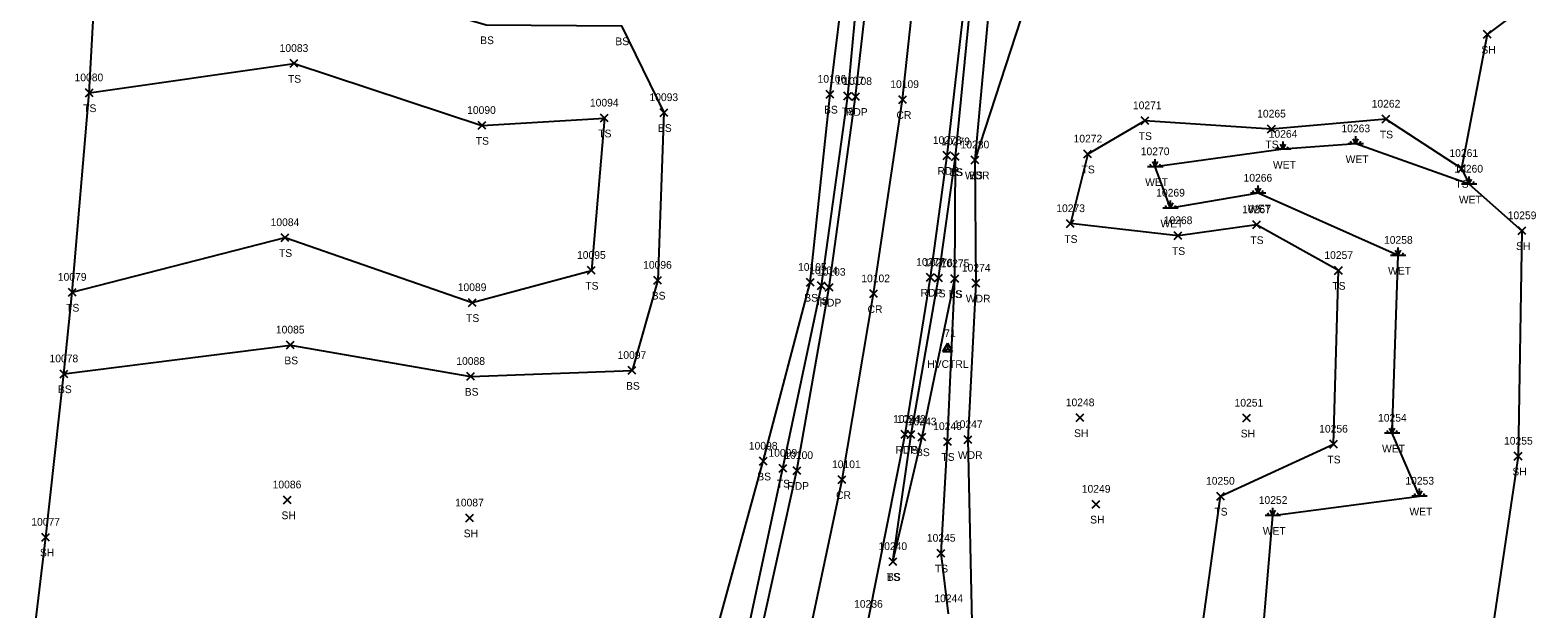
# Model space of a CAD drawing. Extents: x 1482574 to 1485769, y 580696 to 595649.
# Drawn here: x 1484918.2 to 1485309.1, y 580974.9 to 581125.1 of the extents above; entities that cross this region are included whole.
import ezdxf

# ---------------------------------------------------------------- set-up
doc = ezdxf.new("R2010")
doc.units = 0
for name, color, linetype in [('C_A', 7, 'Continuous'), ('C_I', 7, 'Continuous'), ('CPSM', 7, 'Continuous'), ('L_A', 7, 'Continuous'), ('L_I', 7, 'Continuous'), ('L_TIC', 7, 'Continuous'), ('LAWA', 7, 'Continuous'), ('LELB', 7, 'Continuous'), ('LSOGP', 7, 'Continuous'), ('LWET', 7, 'Continuous'), ('P_A', 7, 'Continuous'), ('P_I', 7, 'Continuous'), ('P_TIC', 7, 'Continuous'), ('PET', 7, 'Continuous'), ('PRC', 7, 'Continuous'), ('R_I', 7, 'Continuous')]:
    doc.layers.add(name, color=color, linetype=linetype)

msp = doc.modelspace()

# ---------------------------------------------------------------- linework, layer by layer
at = {"layer": 'CPSM'}
for p, q in [((1485154.86, 581041.75), (1485156.11, 581043.92)), ((1485154.86, 581041.75), (1485156.11, 581042.47)), ((1485154.86, 581041.75), (1485157.36, 581041.75)), ((1485157.36, 581041.75), (1485156.11, 581043.92)), ((1485156.11, 581042.47), (1485156.11, 581043.92)), ((1485156.11, 581042.47), (1485156.11, 581042.47)), ((1485156.11, 581042.47), (1485157.36, 581041.75))]:
    msp.add_line(p, q, dxfattribs=at)
at = {"layer": 'L_TIC'}
for points in [[(1485295, 581123.04), (1485297, 581125.04)], [(1485297, 581123.04), (1485295, 581125.04)], [(1484985.62, 581115.48), (1484987.62, 581117.48)], [(1484987.62, 581115.48), (1484985.62, 581117.48)], [(1484932.52, 581107.86), (1484934.52, 581109.86)], [(1484934.52, 581107.86), (1484932.52, 581109.86)], [(1485124.6, 581107.49), (1485126.6, 581109.49)], [(1485126.6, 581107.49), (1485124.6, 581109.49)], [(1485129.19, 581107.03), (1485131.19, 581109.03)], [(1485131.19, 581107.03), (1485129.19, 581109.03)], [(1485081.52, 581102.72), (1485083.52, 581104.72)], [(1485083.52, 581102.72), (1485081.52, 581104.72)], [(1485034.33, 581099.39), (1485036.33, 581101.39)], [(1485036.33, 581099.39), (1485034.33, 581101.39)], [(1485066.08, 581101.31), (1485068.08, 581103.31)], [(1485068.08, 581101.31), (1485066.08, 581103.31)], [(1485206.23, 581100.62), (1485208.23, 581102.62)], [(1485208.23, 581100.62), (1485206.23, 581102.62)], [(1485239.07, 581098.46), (1485241.07, 581100.46)], [(1485241.07, 581098.46), (1485239.07, 581100.46)], [(1485268.75, 581101.04), (1485270.75, 581103.04)], [(1485270.75, 581101.04), (1485268.75, 581103.04)], [(1485157.09, 581091.27), (1485159.09, 581093.27)], [(1485159.09, 581091.27), (1485157.09, 581093.27)], [(1485157.09, 581091.27), (1485159.09, 581093.27)], [(1485159.09, 581091.27), (1485157.09, 581093.27)], [(1485162.19, 581090.44), (1485164.19, 581092.44)], [(1485164.19, 581090.44), (1485162.19, 581092.44)], [(1485162.19, 581090.44), (1485164.19, 581092.44)], [(1485164.19, 581090.44), (1485162.19, 581092.44)], [(1485191.41, 581091.98), (1485193.41, 581093.98)], [(1485193.41, 581091.98), (1485191.41, 581093.98)], [(1485288.35, 581088.23), (1485290.35, 581090.23)], [(1485290.35, 581088.23), (1485288.35, 581090.23)], [(1485186.93, 581073.91), (1485188.93, 581075.91)], [(1485188.93, 581073.91), (1485186.93, 581075.91)], [(1485186.93, 581073.91), (1485188.93, 581075.91)], [(1485188.93, 581073.91), (1485186.93, 581075.91)], [(1485214.84, 581070.79), (1485216.84, 581072.79)], [(1485216.84, 581070.79), (1485214.84, 581072.79)], [(1485235.19, 581073.62), (1485237.19, 581075.62)], [(1485237.19, 581073.62), (1485235.19, 581075.62)], [(1485303.99, 581072.07), (1485305.99, 581074.07)], [(1485305.99, 581072.07), (1485303.99, 581074.07)], [(1484983.28, 581070.28), (1484985.28, 581072.28)], [(1484985.28, 581070.28), (1484983.28, 581072.28)], [(1485062.73, 581061.78), (1485064.73, 581063.78)], [(1485064.73, 581061.78), (1485062.73, 581063.78)], [(1485062.73, 581061.78), (1485064.73, 581063.78)], [(1485064.73, 581061.78), (1485062.73, 581063.78)], [(1485079.92, 581059.22), (1485081.92, 581061.22)], [(1485081.92, 581059.22), (1485079.92, 581061.22)], [(1485152.71, 581059.8), (1485154.71, 581061.8)], [(1485154.71, 581059.8), (1485152.71, 581061.8)], [(1485156.95, 581059.62), (1485158.95, 581061.62)], [(1485158.95, 581059.62), (1485156.95, 581061.62)], [(1485156.95, 581059.62), (1485158.95, 581061.62)], [(1485158.95, 581059.62), (1485156.95, 581061.62)], [(1485256.44, 581061.76), (1485258.44, 581063.76)], [(1485258.44, 581061.76), (1485256.44, 581063.76)], [(1484928.1, 581056.09), (1484930.1, 581058.09)], [(1484930.1, 581056.09), (1484928.1, 581058.09)], [(1485119.47, 581058.67), (1485121.47, 581060.67)], [(1485121.47, 581058.67), (1485119.47, 581060.67)], [(1485122.36, 581057.79), (1485124.36, 581059.79)], [(1485124.36, 581057.79), (1485122.36, 581059.79)], [(1485162.44, 581058.47), (1485164.44, 581060.47)], [(1485164.44, 581058.47), (1485162.44, 581060.47)], [(1485031.81, 581053.41), (1485033.81, 581055.41)], [(1485033.81, 581053.41), (1485031.81, 581055.41)], [(1484984.65, 581042.41), (1484986.65, 581044.41)], [(1484986.65, 581042.41), (1484984.65, 581044.41)], [(1485073.25, 581035.82), (1485075.25, 581037.82)], [(1485075.25, 581035.82), (1485073.25, 581037.82)], [(1485073.25, 581035.82), (1485075.25, 581037.82)], [(1485075.25, 581035.82), (1485073.25, 581037.82)], [(1484925.95, 581034.93), (1484927.95, 581036.93)], [(1484927.95, 581034.93), (1484925.95, 581036.93)], [(1485031.43, 581034.26), (1485033.43, 581036.26)], [(1485033.43, 581034.26), (1485031.43, 581036.26)], [(1485189.39, 581023.53), (1485191.39, 581025.53)], [(1485191.39, 581023.53), (1485189.39, 581025.53)], [(1485232.59, 581023.44), (1485234.59, 581025.44)], [(1485234.59, 581023.44), (1485232.59, 581025.44)], [(1485145.62, 581019.2), (1485147.62, 581021.2)], [(1485147.62, 581019.2), (1485145.62, 581021.2)], [(1485148.44, 581018.58), (1485150.44, 581020.58)], [(1485150.44, 581018.58), (1485148.44, 581020.58)], [(1485155.07, 581017.36), (1485157.07, 581019.36)], [(1485157.07, 581017.36), (1485155.07, 581019.36)], [(1485160.39, 581017.87), (1485162.39, 581019.87)], [(1485162.39, 581017.87), (1485160.39, 581019.87)], [(1485255.15, 581016.69), (1485257.15, 581018.69)], [(1485257.15, 581016.69), (1485255.15, 581018.69)], [(1485107.28, 581012.28), (1485109.28, 581014.28)], [(1485109.28, 581012.28), (1485107.28, 581014.28)], [(1485303.03, 581013.57), (1485305.03, 581015.57)], [(1485305.03, 581013.57), (1485303.03, 581015.57)], [(1485112.38, 581010.44), (1485114.38, 581012.44)], [(1485114.38, 581010.44), (1485112.38, 581012.44)], [(1484983.86, 581002.22), (1484985.86, 581004.22)], [(1484985.86, 581002.22), (1484983.86, 581004.22)], [(1485193.55, 581001.1), (1485195.55, 581003.1)], [(1485195.55, 581001.1), (1485193.55, 581003.1)], [(1485225.85, 581003.17), (1485227.85, 581005.17)], [(1485227.85, 581003.17), (1485225.85, 581005.17)], [(1485031.12, 580997.53), (1485033.12, 580999.53)], [(1485033.12, 580997.53), (1485031.12, 580999.53)], [(1484921.23, 580992.54), (1484923.23, 580994.54)], [(1484923.23, 580992.54), (1484921.23, 580994.54)], [(1485140.9, 580986.21), (1485142.9, 580988.21)], [(1485142.9, 580986.21), (1485140.9, 580988.21)], [(1485140.9, 580986.21), (1485142.9, 580988.21)], [(1485142.9, 580986.21), (1485140.9, 580988.21)], [(1485153.37, 580988.39), (1485155.37, 580990.39)], [(1485155.37, 580988.39), (1485153.37, 580990.39)]]:
    msp.add_lwpolyline(points, dxfattribs=at)
at = {"layer": 'LAWA'}
msp.add_lwpolyline([(1485090.09, 580767.38), (1485113.93, 580805.62), (1485124.67, 580844.97), (1485127.36, 580859.71), (1485132.08, 580862.45), (1485132.47, 580865.93), (1485133.13, 580868.32), (1485135.53, 580873.95), (1485147.16, 580875.13), (1485157.85, 580878.44), (1485151.2, 580888.48), (1485151.29, 580905.75), (1485152.48, 580913.28), (1485162.05, 580941.52), (1485162.56, 580967.49), (1485161.39, 581018.87), (1485163.44, 581059.47), (1485163.19, 581091.44), (1485177.83, 581136.41)], dxfattribs=at)
at = {"layer": 'LELB'}
for points in [[(1484935.24, 581139.98), (1484986.16, 581141.34), (1485036.42, 581126.5), (1485071.48, 581126.23), (1485082.52, 581103.72), (1485080.92, 581060.22), (1485074.25, 581036.82)], [(1485046.94, 580777), (1485062.94, 580821.64), (1485067.85, 580840.24), (1485070.56, 580856.81), (1485072.31, 580868.2), (1485086.48, 580909.37), (1485099.6, 580947.35), (1485113.38, 581011.44), (1485123.36, 581058.79), (1485130.19, 581108.03), (1485133.21, 581140.81)], [(1485057.25, 580844.65), (1485057.47, 580862.8), (1485078.43, 580909.86), (1485087.41, 580935.49), (1485090.66, 580949.04), (1485108.28, 581013.28), (1485120.47, 581059.67), (1485125.6, 581108.49), (1485129.71, 581141.49)], [(1485141.9, 580987.21), (1485146.62, 581020.2), (1485153.71, 581060.8), (1485158.09, 581092.27), (1485162.46, 581136.34)], [(1485163.19, 581091.44), (1485167.29, 581135.66)], [(1484933.52, 581108.86), (1484986.62, 581116.48), (1485035.33, 581100.39), (1485067.08, 581102.31), (1485063.73, 581062.78)], [(1485289.35, 581089.23), (1485269.75, 581102.04), (1485240.07, 581099.46), (1485207.23, 581101.62), (1485192.41, 581092.98), (1485187.93, 581074.91)], [(1485141.9, 580987.21), (1485149.44, 581019.58), (1485157.95, 581060.62), (1485158.09, 581092.27)], [(1485162.05, 580941.52), (1485171.27, 580923.41), (1485194.61, 580922.33), (1485214.94, 580901.52), (1485236.67, 580900.44), (1485219.95, 580918.95), (1485218.06, 580940.65), (1485226.85, 581004.17), (1485256.15, 581017.69), (1485257.44, 581062.76), (1485236.19, 581074.62), (1485215.84, 581071.79), (1485187.93, 581074.91)], [(1484929.1, 581057.09), (1484984.28, 581071.28), (1485032.81, 581054.41), (1485063.73, 581062.78)], [(1485156.31, 580973.68), (1485154.37, 580989.39), (1485156.07, 581018.36), (1485157.95, 581060.62)], [(1484926.95, 581035.93), (1484985.65, 581043.41), (1485032.43, 581035.26), (1485074.25, 581036.82)]]:
    msp.add_lwpolyline(points, dxfattribs=at)
at = {"layer": 'LSOGP'}
for points in [[(1484918.18, 580959.77), (1484922.23, 580993.54), (1484926.95, 581035.93), (1484929.1, 581057.09), (1484933.52, 581108.86), (1484935.24, 581139.98)], [(1485309.13, 581133.94), (1485296, 581124.04), (1485289.35, 581089.23), (1485291.28, 581085.17), (1485304.99, 581073.07), (1485304.03, 581014.57), (1485293.7, 580945.29)]]:
    msp.add_lwpolyline(points, dxfattribs=at)
at = {"layer": 'LWET'}
for p, q in [((1485243.06, 581094.21), (1485243.06, 581096.21)), ((1485260.92, 581095.63), (1485260.58, 581096.29)), ((1485261.92, 581095.63), (1485261.25, 581096.96)), ((1485261.92, 581095.63), (1485261.92, 581097.63)), ((1485261.92, 581095.63), (1485262.58, 581096.96)), ((1485262.92, 581095.63), (1485263.25, 581096.29)), ((1485245.06, 581094.21), (1485241.06, 581094.21)), ((1485242.06, 581094.21), (1485241.73, 581094.87)), ((1485243.06, 581094.21), (1485242.39, 581095.54)), ((1485243.06, 581094.21), (1485243.73, 581095.54)), ((1485244.06, 581094.21), (1485244.39, 581094.87)), ((1485263.92, 581095.63), (1485259.92, 581095.63)), ((1485211.93, 581089.68), (1485207.93, 581089.68)), ((1485211.93, 581089.68), (1485207.93, 581089.68)), ((1485208.93, 581089.68), (1485208.59, 581090.35)), ((1485208.93, 581089.68), (1485208.59, 581090.35)), ((1485209.93, 581089.68), (1485209.26, 581091.02)), ((1485209.93, 581089.68), (1485209.26, 581091.02)), ((1485209.93, 581089.68), (1485209.93, 581091.68)), ((1485209.93, 581089.68), (1485209.93, 581091.68)), ((1485209.93, 581089.68), (1485210.59, 581091.02)), ((1485209.93, 581089.68), (1485210.59, 581091.02)), ((1485210.93, 581089.68), (1485211.26, 581090.35)), ((1485210.93, 581089.68), (1485211.26, 581090.35)), ((1485236.59, 581082.82), (1485236.59, 581084.82)), ((1485293.29, 581085.17), (1485289.29, 581085.17)), ((1485290.29, 581085.17), (1485289.95, 581085.83)), ((1485291.29, 581085.17), (1485290.62, 581086.5)), ((1485291.29, 581085.17), (1485291.29, 581087.17)), ((1485291.29, 581085.17), (1485291.95, 581086.5)), ((1485292.29, 581085.17), (1485292.62, 581085.83)), ((1485213.9, 581078.95), (1485213.9, 581080.95)), ((1485238.59, 581082.82), (1485234.59, 581082.82)), ((1485235.59, 581082.82), (1485235.26, 581083.48)), ((1485236.59, 581082.82), (1485235.92, 581084.15)), ((1485236.59, 581082.82), (1485237.26, 581084.15)), ((1485237.59, 581082.82), (1485237.92, 581083.48)), ((1485215.9, 581078.95), (1485211.9, 581078.95)), ((1485212.9, 581078.95), (1485212.56, 581079.62)), ((1485213.9, 581078.95), (1485213.23, 581080.28)), ((1485213.9, 581078.95), (1485214.56, 581080.28)), ((1485214.9, 581078.95), (1485215.23, 581079.62)), ((1485272.91, 581066.69), (1485272.91, 581068.69)), ((1485274.91, 581066.69), (1485270.91, 581066.69)), ((1485271.91, 581066.69), (1485271.58, 581067.35)), ((1485272.91, 581066.69), (1485272.25, 581068.02)), ((1485272.91, 581066.69), (1485273.58, 581068.02)), ((1485273.91, 581066.69), (1485274.25, 581067.35)), ((1485271.36, 581020.53), (1485270.69, 581021.87)), ((1485271.36, 581020.53), (1485271.36, 581022.53)), ((1485271.36, 581020.53), (1485272.02, 581021.87)), ((1485273.36, 581020.53), (1485269.36, 581020.53)), ((1485270.36, 581020.53), (1485270.02, 581021.2)), ((1485272.36, 581020.53), (1485272.69, 581021.2)), ((1485278.45, 581004.2), (1485278.45, 581006.2)), ((1485280.45, 581004.2), (1485276.45, 581004.2)), ((1485277.45, 581004.2), (1485277.12, 581004.87)), ((1485278.45, 581004.2), (1485277.78, 581005.54)), ((1485278.45, 581004.2), (1485279.12, 581005.54)), ((1485279.45, 581004.2), (1485279.78, 581004.87)), ((1485242.42, 580999.19), (1485238.42, 580999.19)), ((1485239.42, 580999.19), (1485239.08, 580999.86)), ((1485240.42, 580999.19), (1485239.75, 581000.52)), ((1485240.42, 580999.19), (1485240.42, 581001.19)), ((1485240.42, 580999.19), (1485241.08, 581000.52)), ((1485241.42, 580999.19), (1485241.75, 580999.86))]:
    msp.add_line(p, q, dxfattribs=at)
for points in [[(1485291.29, 581085.17), (1485261.92, 581095.63), (1485243.06, 581094.21), (1485209.93, 581089.68)], [(1485236.37, 580950.71), (1485240.42, 580999.19), (1485278.45, 581004.2), (1485271.36, 581020.53), (1485272.91, 581066.69), (1485236.59, 581082.82), (1485213.9, 581078.95), (1485209.93, 581089.68)]]:
    msp.add_lwpolyline(points, dxfattribs=at)
at = {"layer": 'P_TIC'}
for points in [[(1485131.21, 581106.9), (1485133.21, 581108.9)], [(1485133.21, 581106.9), (1485131.21, 581108.9)], [(1485143.4, 581106.11), (1485145.4, 581108.11)], [(1485145.4, 581106.11), (1485143.4, 581108.11)], [(1485154.93, 581091.6), (1485156.93, 581093.6)], [(1485156.93, 581091.6), (1485154.93, 581093.6)], [(1485150.6, 581059.97), (1485152.6, 581061.97)], [(1485152.6, 581059.97), (1485150.6, 581061.97)], [(1485124.37, 581057.41), (1485126.37, 581059.41)], [(1485126.37, 581057.41), (1485124.37, 581059.41)], [(1485135.89, 581055.71), (1485137.89, 581057.71)], [(1485137.89, 581055.71), (1485135.89, 581057.71)], [(1485144.04, 581019.23), (1485146.04, 581021.23)], [(1485146.04, 581019.23), (1485144.04, 581021.23)], [(1485116.02, 581009.84), (1485118.02, 581011.84)], [(1485118.02, 581009.84), (1485116.02, 581011.84)], [(1485127.71, 581007.47), (1485129.71, 581009.47)], [(1485129.71, 581007.47), (1485127.71, 581009.47)]]:
    msp.add_lwpolyline(points, dxfattribs=at)
at = {"layer": 'PET'}
for points in [[(1485050.43, 580776.09), (1485065.96, 580820.78), (1485080.72, 580866.07), (1485093.15, 580908.62), (1485102.74, 580946.52), (1485117.02, 581010.84), (1485125.37, 581058.41), (1485132.21, 581107.9), (1485135.95, 581140.58)], [(1485075.28, 580769.14), (1485087.11, 580802.21), (1485102.51, 580848.51), (1485115.76, 580893.02), (1485126.66, 580933.62), (1485135.55, 580972.24), (1485145.04, 581020.23), (1485151.6, 581060.97), (1485155.93, 581092.6), (1485160.97, 581136.64)]]:
    msp.add_lwpolyline(points, dxfattribs=at)
at = {"layer": 'PRC'}
msp.add_lwpolyline([(1485061.99, 580772.26), (1485077.92, 580817.31), (1485092.35, 580861.47), (1485105.4, 580906.67), (1485114.95, 580943.58), (1485128.71, 581008.47), (1485136.89, 581056.71), (1485144.4, 581107.11), (1485147.83, 581139.16)], dxfattribs=at)

# ---------------------------------------------------------------- texts
at = {"layer": 'C_A'}
msp.add_text('HVCTRL', height=2, dxfattribs=at).set_placement((1485150.8, 581037.47))
at = {"layer": 'C_I'}
msp.add_text('71', height=2, dxfattribs=at).set_placement((1485155.21, 581045.47))
at = {"layer": 'L_A'}
for s, p in [('BS', (1485034.87, 581121.5)), ('BS', (1485069.92, 581121.23)), ('SH', (1485294.49, 581119.04)), ('TS', (1484985.03, 581111.48)), ('TS', (1484931.93, 581103.86)), ('BS', (1485124.04, 581103.49)), ('TS', (1485128.6, 581103.03)), ('BS', (1485080.96, 581098.72)), ('TS', (1485033.73, 581095.39)), ('TS', (1485065.49, 581097.31)), ('TS', (1485205.64, 581096.62)), ('TS', (1485238.48, 581094.46)), ('TS', (1485268.16, 581097.04)), ('WET', (1485259.29, 581090.63)), ('TS', (1485156.5, 581087.27)), ('BS', (1485156.54, 581087.27)), ('WDR', (1485160.56, 581086.44)), ('BS', (1485161.63, 581086.44)), ('TS', (1485190.82, 581087.98)), ('WET', (1485240.44, 581089.21)), ('WET', (1485207.3, 581084.68)), ('WET', (1485207.3, 581084.68)), ('TS', (1485287.76, 581084.23)), ('WET', (1485288.66, 581080.17)), ('WET', (1485233.97, 581077.82)), ('WET', (1485211.28, 581073.95)), ('TS', (1485186.34, 581069.91)), ('TS', (1485186.34, 581069.91)), ('TS', (1485214.25, 581066.79)), ('TS', (1485234.59, 581069.62)), ('SH', (1485303.48, 581068.07)), ('TS', (1484982.69, 581066.28)), ('WET', (1485270.29, 581061.69)), ('TS', (1485062.14, 581057.78)), ('TS', (1485062.14, 581057.78)), ('BS', (1485079.36, 581055.22)), ('TS', (1485152.12, 581055.8)), ('TS', (1485156.36, 581055.62)), ('BS', (1485156.39, 581055.62)), ('TS', (1485255.85, 581057.76)), ('TS', (1484927.51, 581052.09)), ('BS', (1485118.91, 581054.67)), ('TS', (1485121.77, 581053.79)), ('WDR', (1485160.81, 581054.47)), ('TS', (1485031.22, 581049.41)), ('BS', (1484984.09, 581038.41)), ('BS', (1485072.69, 581031.82)), ('BS', (1485072.69, 581031.82)), ('BS', (1484925.39, 581030.93)), ('BS', (1485030.87, 581030.26)), ('SH', (1485188.87, 581019.53)), ('SH', (1485232.08, 581019.44)), ('TS', (1485145.03, 581015.2)), ('BS', (1485147.88, 581014.58)), ('TS', (1485154.48, 581013.36)), ('WDR', (1485158.75, 581013.87)), ('TS', (1485254.56, 581012.69)), ('WET', (1485268.73, 581015.53)), ('BS', (1485106.72, 581008.28)), ('SH', (1485302.52, 581009.57)), ('TS', (1485111.79, 581006.44)), ('SH', (1484983.35, 580998.22)), ('SH', (1485193.04, 580997.1)), ('TS', (1485225.26, 580999.17)), ('WET', (1485275.83, 580999.2)), ('SH', (1485030.6, 580993.53)), ('WET', (1485237.79, 580994.19)), ('SH', (1484920.72, 580988.54)), ('TS', (1485140.31, 580982.21)), ('BS', (1485140.34, 580982.21)), ('TS', (1485152.78, 580984.39))]:
    msp.add_text(s, height=2, dxfattribs=at).set_placement(p)
at = {"layer": 'L_I'}
for s, p in [('10083', (1484982.87, 581119.48)), ('10080', (1484929.69, 581111.86)), ('10106', (1485122.36, 581111.49)), ('10107', (1485127.01, 581111.03)), ('10093', (1485078.77, 581106.72)), ('10090', (1485031.49, 581103.39)), ('10094', (1485063.33, 581105.31)), ('10271', (1485204.13, 581104.62)), ('10265', (1485236.35, 581102.46)), ('10262', (1485266.04, 581105.04)), ('10263', (1485258.2, 581098.63)), ('10279', (1485154.42, 581095.27)), ('10279', (1485154.42, 581095.27)), ('10280', (1485159.44, 581094.44)), ('10280', (1485159.44, 581094.44)), ('10272', (1485188.74, 581095.98)), ('10264', (1485239.34, 581097.21)), ('10270', (1485206.17, 581092.68)), ('10270', (1485206.17, 581092.68)), ('10261', (1485286.2, 581092.23)), ('10260', (1485287.48, 581088.17)), ('10266', (1485232.82, 581085.82)), ('10269', (1485210.17, 581081.95)), ('10273', (1485184.26, 581077.91)), ('10273', (1485184.26, 581077.91)), ('10268', (1485212.12, 581074.79)), ('10267', (1485232.47, 581077.62)), ('10259', (1485301.32, 581076.07)), ('10084', (1484980.53, 581074.28)), ('10258', (1485269.24, 581069.69)), ('10095', (1485059.98, 581065.78)), ('10095', (1485059.98, 581065.78)), ('10096', (1485077.12, 581063.22)), ('10105', (1485117.29, 581062.67)), ('10276', (1485149.99, 581063.8)), ('10275', (1485154.28, 581063.62)), ('10275', (1485154.28, 581063.62)), ('10257', (1485253.77, 581065.76)), ('10079', (1484925.35, 581060.09)), ('10104', (1485120.18, 581061.79)), ('10274', (1485159.77, 581062.47)), ('10089', (1485029.05, 581057.41)), ('10085', (1484981.9, 581046.41)), ('10097', (1485070.5, 581039.82)), ('10097', (1485070.5, 581039.82)), ('10078', (1484923.2, 581038.93)), ('10088', (1485028.68, 581038.26)), ('10248', (1485186.72, 581027.53)), ('10251', (1485230.49, 581027.44)), ('10242', (1485142.95, 581023.2)), ('10243', (1485145.77, 581022.58)), ('10246', (1485152.34, 581021.36)), ('10247', (1485157.72, 581021.87)), ('10256', (1485252.43, 581020.69)), ('10254', (1485267.69, 581023.53)), ('10098', (1485104.54, 581016.28)), ('10255', (1485300.36, 581017.57)), ('10099', (1485109.62, 581014.44)), ('10086', (1484981.06, 581006.22)), ('10249', (1485190.87, 581005.1)), ('10250', (1485223.09, 581007.17)), ('10253', (1485274.78, 581007.2)), ('10087', (1485028.37, 581001.53)), ('10252', (1485236.75, 581002.19)), ('10077', (1484918.48, 580996.54)), ('10245', (1485150.7, 580992.39)), ('10240', (1485138.14, 580990.21)), ('10240', (1485138.14, 580990.21)), ('10244', (1485152.64, 580976.68))]:
    msp.add_text(s, height=2, dxfattribs=at).set_placement(p)
at = {"layer": 'P_A'}
for s, p in [('RDP', (1485129.7, 581102.9)), ('CR', (1485142.83, 581102.11)), ('RDP', (1485153.42, 581087.6)), ('RDP', (1485149.08, 581055.97)), ('RDP', (1485122.86, 581053.41)), ('CR', (1485135.32, 581051.71)), ('RDP', (1485142.53, 581015.23)), ('RDP', (1485114.5, 581005.84)), ('CR', (1485127.15, 581003.47))]:
    msp.add_text(s, height=2, dxfattribs=at).set_placement(p)
at = {"layer": 'P_I'}
for s, p in [('10108', (1485129.03, 581110.9)), ('10109', (1485141.21, 581110.11)), ('10278', (1485152.26, 581095.6)), ('10277', (1485147.93, 581063.97)), ('10103', (1485122.19, 581061.41)), ('10102', (1485133.7, 581059.71)), ('10241', (1485141.94, 581023.23)), ('10100', (1485113.75, 581013.84)), ('10101', (1485126.1, 581011.47)), ('10236', (1485131.83, 580975.24))]:
    msp.add_text(s, height=2, dxfattribs=at).set_placement(p)
at = {"layer": 'R_I'}
msp.add_text('10236', height=2, dxfattribs=at).set_placement((1485131.83, 580975.24))

doc.saveas('drawing.dxf')
